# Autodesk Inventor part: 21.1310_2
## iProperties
Created: 2006-12
Part Number: 21.1310_2
Document SubType Name: Modeling
Designer: Andy Moles
Material: Steel, Mild
Density: 7.86 g/cm^3
Vendor: S
Mass: 5.88397 g
Surface Area: 8.40555 cm^2
Volume: 0.748597 cm^3
Author: Andy Moles
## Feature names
1. Extrusion1
2. Revolution1
3. Extrusion3
4. Fillet2
5. Fillet3
